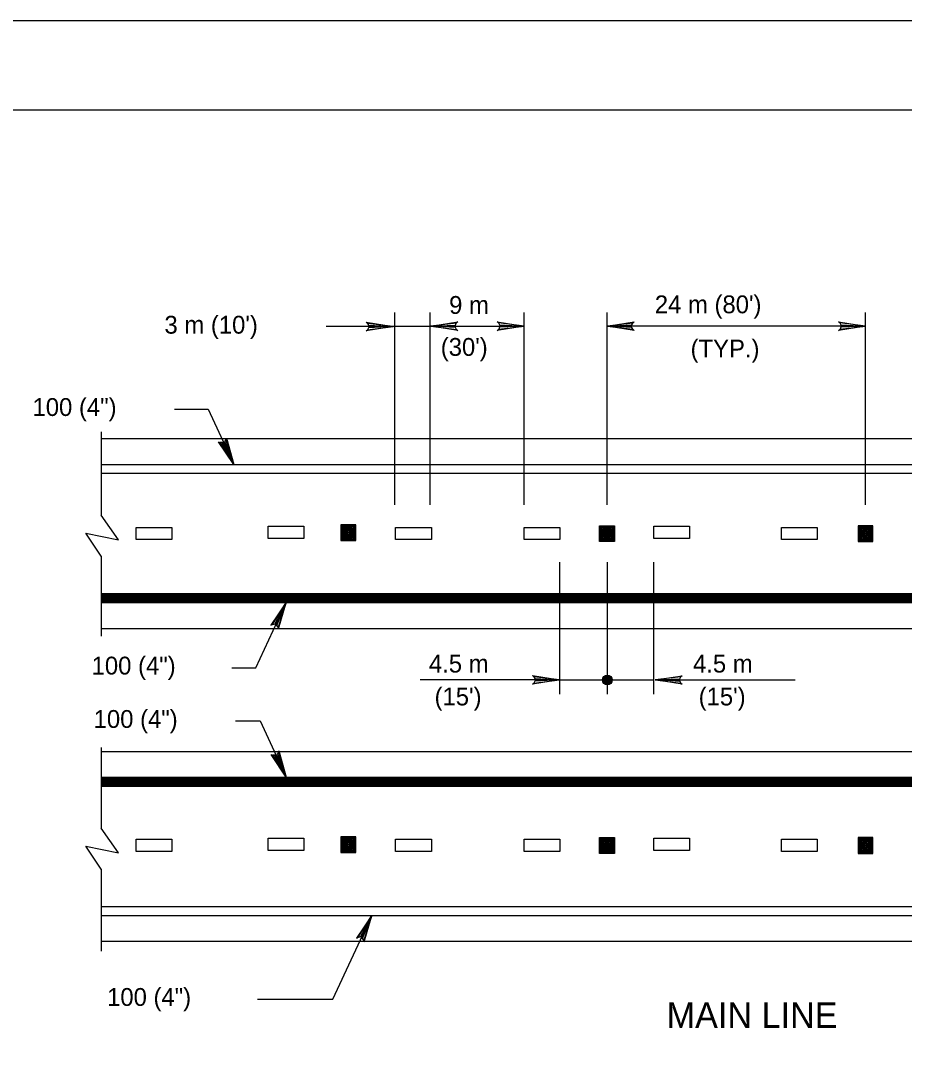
# Model space of a CAD drawing. Extents: x 639362 to 641108, y 298458 to 299646.
# Drawn here: x 639830.9 to 639979.6, y 299473.3 to 299645.6 of the extents above; entities that cross this region are included whole.
import ezdxf

# ---------------------------------------------------------------- set-up
doc = ezdxf.new("R2010")
doc.units = 0
for name, color, linetype in [('1', 7, 'Continuous'), ('2', 7, 'Continuous'), ('PLT-BNDY', 7, 'Continuous')]:
    doc.layers.add(name, color=color, linetype=linetype)

msp = doc.modelspace()

# ---------------------------------------------------------------- linework, layer by layer
at = {"layer": '1'}
msp.add_line((639402.31, 299630.63), (640188.31, 299630.63), dxfattribs=at)
at = {"layer": '2'}
for p, q in [((639893.88, 299564.2), (639893.88, 299596.53)), ((639899.82, 299564.2), (639899.82, 299596.53)), ((639915.64, 299564.2), (639915.64, 299596.53)), ((639929.6, 299564.2), (639929.6, 299596.53)), ((639973.04, 299564.2), (639973.04, 299596.53)), ((639882.34, 299594.23), (639899.82, 299594.23)), ((639899.82, 299594.23), (639915.64, 299594.23)), ((639973.04, 299594.23), (639929.6, 299594.23)), ((639856.81, 299580.26), (639862.49, 299580.26)), ((639862.49, 299580.26), (639866.8, 299570.98)), ((639844.48, 299576.44), (639844.48, 299562.41)), ((639844.48, 299575.33), (640078.99, 299575.33)), ((639844.48, 299570.98), (640078.99, 299570.98)), ((639844.48, 299569.48), (640078.99, 299569.48)), ((639847.43, 299558.27), (639844.48, 299562.41)), ((639850.37, 299558.33), (639850.37, 299560.39)), ((639850.37, 299560.39), (639856.39, 299560.39)), ((639856.39, 299560.39), (639856.39, 299558.33)), ((639872.56, 299558.51), (639872.56, 299560.58)), ((639872.56, 299560.58), (639878.58, 299560.58)), ((639878.58, 299560.58), (639878.58, 299558.51)), ((639887.32, 299560.81), (639884.82, 299560.81)), ((639884.82, 299560.81), (639884.82, 299558.16)), ((639887.13, 299560.68), (639885.01, 299560.68)), ((639885.01, 299560.68), (639885.01, 299558.29)), ((639886.96, 299560.51), (639885.18, 299560.51)), ((639885.18, 299560.51), (639885.18, 299558.47)), ((639886.78, 299560.33), (639885.36, 299560.33)), ((639885.36, 299560.33), (639885.36, 299558.64)), ((639886.6, 299560.15), (639885.54, 299560.15)), ((639885.54, 299560.15), (639885.54, 299558.82)), ((639886.6, 299558.82), (639886.6, 299560.15)), ((639886.78, 299558.64), (639886.78, 299560.33)), ((639886.96, 299558.47), (639886.96, 299560.51)), ((639887.13, 299558.29), (639887.13, 299560.68)), ((639887.32, 299558.16), (639887.32, 299560.81)), ((639894.01, 299558.33), (639894.01, 299560.39)), ((639894.01, 299560.39), (639900.02, 299560.39)), ((639900.02, 299560.39), (639900.02, 299558.33)), ((639915.64, 299558.33), (639915.64, 299560.39)), ((639915.64, 299560.39), (639921.65, 299560.39)), ((639921.65, 299560.39), (639921.65, 299558.33)), ((639928.31, 299560.65), (639930.81, 299560.65)), ((639928.31, 299558), (639928.31, 299560.65)), ((639928.5, 299560.52), (639930.63, 299560.52)), ((639928.5, 299558.12), (639928.5, 299560.52)), ((639928.68, 299560.34), (639930.45, 299560.34)), ((639928.68, 299558.3), (639928.68, 299560.34)), ((639928.85, 299560.16), (639930.27, 299560.16)), ((639928.85, 299558.48), (639928.85, 299560.16)), ((639930.27, 299560.16), (639930.27, 299558.48)), ((639930.45, 299560.34), (639930.45, 299558.3)), ((639930.63, 299560.52), (639930.63, 299558.12)), ((639930.81, 299560.65), (639930.81, 299558)), ((639937.42, 299558.51), (639937.42, 299560.58)), ((639937.42, 299560.58), (639943.44, 299560.58)), ((639943.44, 299560.58), (639943.44, 299558.51)), ((639958.88, 299558.33), (639958.88, 299560.39)), ((639958.88, 299560.39), (639964.89, 299560.39)), ((639964.89, 299560.39), (639964.89, 299558.33)), ((639974.28, 299560.65), (639971.78, 299560.65)), ((639971.78, 299560.65), (639971.78, 299558)), ((639974.09, 299560.52), (639971.96, 299560.52)), ((639971.96, 299560.52), (639971.96, 299558.12)), ((639973.92, 299560.34), (639972.14, 299560.34)), ((639972.14, 299560.34), (639972.14, 299558.3)), ((639973.74, 299560.16), (639972.32, 299560.16)), ((639972.32, 299560.16), (639972.32, 299558.48)), ((639973.74, 299558.48), (639973.74, 299560.16)), ((639973.92, 299558.3), (639973.92, 299560.34)), ((639974.09, 299558.12), (639974.09, 299560.52)), ((639974.28, 299558), (639974.28, 299560.65)), ((639844.48, 299555.54), (639841.91, 299559.41)), ((639841.91, 299559.41), (639847.43, 299558.27)), ((639878.58, 299558.51), (639872.56, 299558.51)), ((639885.18, 299558.47), (639886.96, 299558.47)), ((639885.36, 299558.64), (639886.78, 299558.64)), ((639885.54, 299558.82), (639886.6, 299558.82)), ((639885.71, 299559.97), (639885.71, 299559)), ((639886.43, 299559.97), (639885.71, 299559.97)), ((639885.71, 299559), (639886.43, 299559)), ((639886.25, 299559.79), (639885.89, 299559.79)), ((639885.89, 299559.79), (639885.89, 299559.17)), ((639885.89, 299559.17), (639886.25, 299559.17)), ((639886.07, 299559.62), (639886.07, 299559.35)), ((639886.25, 299559.17), (639886.25, 299559.79)), ((639886.43, 299559), (639886.43, 299559.97)), ((639930.27, 299558.48), (639928.85, 299558.48)), ((639929.03, 299559.99), (639930.1, 299559.99)), ((639929.03, 299558.66), (639929.03, 299559.99)), ((639930.1, 299558.66), (639929.03, 299558.66)), ((639929.21, 299558.83), (639929.21, 299559.81)), ((639929.21, 299559.81), (639929.92, 299559.81)), ((639929.92, 299558.83), (639929.21, 299558.83)), ((639929.39, 299559.63), (639929.74, 299559.63)), ((639929.39, 299559.01), (639929.39, 299559.63)), ((639929.74, 299559.01), (639929.39, 299559.01)), ((639929.56, 299559.45), (639929.56, 299559.19)), ((639929.74, 299559.63), (639929.74, 299559.01)), ((639929.92, 299559.81), (639929.92, 299558.83)), ((639930.1, 299559.99), (639930.1, 299558.66)), ((639943.44, 299558.51), (639937.42, 299558.51)), ((639972.32, 299558.48), (639973.74, 299558.48)), ((639973.56, 299559.99), (639972.5, 299559.99)), ((639972.5, 299559.99), (639972.5, 299558.66)), ((639972.5, 299558.66), (639973.56, 299558.66)), ((639972.67, 299559.81), (639972.67, 299558.83)), ((639973.38, 299559.81), (639972.67, 299559.81)), ((639972.67, 299558.83), (639973.38, 299558.83)), ((639973.2, 299559.63), (639972.85, 299559.63)), ((639972.85, 299559.63), (639972.85, 299559.01)), ((639972.85, 299559.01), (639973.2, 299559.01)), ((639973.03, 299559.45), (639973.03, 299559.19)), ((639973.2, 299559.01), (639973.2, 299559.63)), ((639973.38, 299558.83), (639973.38, 299559.81)), ((639973.56, 299558.66), (639973.56, 299559.99)), ((639856.39, 299558.33), (639850.37, 299558.33)), ((639884.82, 299558.16), (639887.32, 299558.16)), ((639885.01, 299558.29), (639887.13, 299558.29)), ((639900.02, 299558.33), (639894.01, 299558.33)), ((639921.65, 299558.33), (639915.64, 299558.33)), ((639930.81, 299558), (639928.31, 299558)), ((639930.63, 299558.12), (639928.5, 299558.12)), ((639930.45, 299558.3), (639928.68, 299558.3)), ((639964.89, 299558.33), (639958.88, 299558.33)), ((639971.78, 299558), (639974.28, 299558)), ((639971.96, 299558.12), (639974.09, 299558.12)), ((639972.14, 299558.3), (639973.92, 299558.3)), ((639844.48, 299555.54), (639844.48, 299542.1)), ((639921.57, 299554.52), (639921.57, 299532.35)), ((639929.6, 299554.52), (639929.6, 299532.35)), ((639937.4, 299554.52), (639937.4, 299532.35)), ((639844.48, 299549.24), (640078.99, 299549.24)), ((639844.48, 299549.09), (640078.99, 299549.09)), ((639844.48, 299548.94), (640078.99, 299548.94)), ((639844.48, 299548.79), (640078.99, 299548.79)), ((639844.48, 299548.64), (640078.99, 299548.64)), ((639844.48, 299548.49), (640078.99, 299548.49)), ((639844.48, 299548.34), (640078.99, 299548.34)), ((639844.48, 299548.19), (640078.99, 299548.19)), ((639844.48, 299548.04), (640078.99, 299548.04)), ((639844.48, 299547.89), (640078.99, 299547.89)), ((639844.48, 299547.74), (640078.99, 299547.74)), ((639870.5, 299536.76), (639875.59, 299547.74)), ((639844.48, 299543.39), (640078.99, 299543.39)), ((639866.45, 299536.76), (639870.5, 299536.76)), ((639921.57, 299534.72), (639898.14, 299534.72)), ((639921.57, 299534.72), (639937.4, 299534.72)), ((639937.63, 299534.72), (639961.2, 299534.72)), ((639867.08, 299527.87), (639871.22, 299527.87)), ((639871.22, 299527.87), (639875.63, 299518.37)), ((639844.48, 299523.39), (639844.48, 299509.8)), ((639844.48, 299522.72), (640078.99, 299522.72)), ((639844.48, 299518.37), (640078.99, 299518.37)), ((639844.48, 299518.22), (640078.99, 299518.22)), ((639844.48, 299518.07), (640078.99, 299518.07)), ((639844.48, 299517.92), (640078.99, 299517.92)), ((639844.48, 299517.77), (640078.99, 299517.77)), ((639844.48, 299517.62), (640078.99, 299517.62)), ((639844.48, 299517.47), (640078.99, 299517.47)), ((639844.48, 299517.32), (640078.99, 299517.32)), ((639844.48, 299517.17), (640078.99, 299517.17)), ((639844.48, 299517.02), (640078.99, 299517.02)), ((639844.48, 299516.87), (640078.99, 299516.87)), ((639847.43, 299505.67), (639844.48, 299509.8)), ((639844.48, 299502.93), (639841.91, 299506.8)), ((639841.91, 299506.8), (639847.43, 299505.67)), ((639850.37, 299505.88), (639850.37, 299507.94)), ((639850.37, 299507.94), (639856.39, 299507.94)), ((639856.39, 299507.94), (639856.39, 299505.88)), ((639872.56, 299506.07), (639872.56, 299508.13)), ((639872.56, 299508.13), (639878.58, 299508.13)), ((639878.58, 299508.13), (639878.58, 299506.07)), ((639887.32, 299508.37), (639884.82, 299508.37)), ((639884.82, 299508.37), (639884.82, 299505.71)), ((639887.13, 299508.24), (639885.01, 299508.24)), ((639885.01, 299508.24), (639885.01, 299505.84)), ((639886.96, 299508.06), (639885.18, 299508.06)), ((639885.18, 299508.06), (639885.18, 299506.02)), ((639886.78, 299507.88), (639885.36, 299507.88)), ((639885.36, 299507.88), (639885.36, 299506.2)), ((639886.6, 299507.7), (639885.54, 299507.7)), ((639885.54, 299507.7), (639885.54, 299506.37)), ((639885.71, 299507.53), (639885.71, 299506.55)), ((639886.43, 299507.53), (639885.71, 299507.53)), ((639886.25, 299507.35), (639885.89, 299507.35)), ((639885.89, 299507.35), (639885.89, 299506.73)), ((639885.89, 299506.73), (639886.25, 299506.73)), ((639886.07, 299507.17), (639886.07, 299506.91)), ((639886.25, 299506.73), (639886.25, 299507.35)), ((639886.43, 299506.55), (639886.43, 299507.53)), ((639886.6, 299506.37), (639886.6, 299507.7)), ((639886.78, 299506.2), (639886.78, 299507.88)), ((639886.96, 299506.02), (639886.96, 299508.06)), ((639887.13, 299505.84), (639887.13, 299508.24)), ((639887.32, 299505.71), (639887.32, 299508.37)), ((639894.01, 299505.88), (639894.01, 299507.94)), ((639894.01, 299507.94), (639900.02, 299507.94)), ((639900.02, 299507.94), (639900.02, 299505.88)), ((639915.64, 299505.88), (639915.64, 299507.94)), ((639915.64, 299507.94), (639921.65, 299507.94)), ((639921.65, 299507.94), (639921.65, 299505.88)), ((639928.31, 299508.21), (639930.81, 299508.21)), ((639928.31, 299505.55), (639928.31, 299508.21)), ((639928.5, 299508.07), (639930.63, 299508.07)), ((639928.5, 299505.68), (639928.5, 299508.07)), ((639928.68, 299507.9), (639930.45, 299507.9)), ((639928.68, 299505.86), (639928.68, 299507.9)), ((639928.85, 299507.72), (639930.27, 299507.72)), ((639928.85, 299506.03), (639928.85, 299507.72)), ((639929.03, 299507.54), (639930.1, 299507.54)), ((639929.03, 299506.21), (639929.03, 299507.54)), ((639929.21, 299506.39), (639929.21, 299507.36)), ((639929.21, 299507.36), (639929.92, 299507.36)), ((639929.39, 299507.19), (639929.74, 299507.19)), ((639929.39, 299506.57), (639929.39, 299507.19)), ((639929.56, 299507.01), (639929.56, 299506.74)), ((639929.74, 299507.19), (639929.74, 299506.57)), ((639929.92, 299507.36), (639929.92, 299506.39)), ((639930.1, 299507.54), (639930.1, 299506.21)), ((639930.27, 299507.72), (639930.27, 299506.03)), ((639930.45, 299507.9), (639930.45, 299505.86)), ((639930.63, 299508.07), (639930.63, 299505.68)), ((639930.81, 299508.21), (639930.81, 299505.55)), ((639937.42, 299506.07), (639937.42, 299508.13)), ((639937.42, 299508.13), (639943.44, 299508.13)), ((639943.44, 299508.13), (639943.44, 299506.07)), ((639958.88, 299505.88), (639958.88, 299507.94)), ((639958.88, 299507.94), (639964.89, 299507.94)), ((639964.89, 299507.94), (639964.89, 299505.88)), ((639974.28, 299508.21), (639971.78, 299508.21)), ((639971.78, 299508.21), (639971.78, 299505.55)), ((639974.09, 299508.07), (639971.96, 299508.07)), ((639971.96, 299508.07), (639971.96, 299505.68)), ((639973.92, 299507.9), (639972.14, 299507.9)), ((639972.14, 299507.9), (639972.14, 299505.86)), ((639973.74, 299507.72), (639972.32, 299507.72)), ((639972.32, 299507.72), (639972.32, 299506.03)), ((639973.56, 299507.54), (639972.5, 299507.54)), ((639972.5, 299507.54), (639972.5, 299506.21)), ((639972.67, 299507.36), (639972.67, 299506.39)), ((639973.38, 299507.36), (639972.67, 299507.36)), ((639973.2, 299507.19), (639972.85, 299507.19)), ((639972.85, 299507.19), (639972.85, 299506.57)), ((639973.03, 299507.01), (639973.03, 299506.74)), ((639973.2, 299506.57), (639973.2, 299507.19)), ((639973.38, 299506.39), (639973.38, 299507.36)), ((639973.56, 299506.21), (639973.56, 299507.54)), ((639973.74, 299506.03), (639973.74, 299507.72)), ((639973.92, 299505.86), (639973.92, 299507.9)), ((639974.09, 299505.68), (639974.09, 299508.07)), ((639974.28, 299505.55), (639974.28, 299508.21)), ((639856.39, 299505.88), (639850.37, 299505.88)), ((639878.58, 299506.07), (639872.56, 299506.07)), ((639884.82, 299505.71), (639887.32, 299505.71)), ((639885.01, 299505.84), (639887.13, 299505.84)), ((639885.18, 299506.02), (639886.96, 299506.02)), ((639885.36, 299506.2), (639886.78, 299506.2)), ((639885.54, 299506.37), (639886.6, 299506.37)), ((639885.71, 299506.55), (639886.43, 299506.55)), ((639900.02, 299505.88), (639894.01, 299505.88)), ((639921.65, 299505.88), (639915.64, 299505.88)), ((639930.81, 299505.55), (639928.31, 299505.55)), ((639930.63, 299505.68), (639928.5, 299505.68)), ((639930.45, 299505.86), (639928.68, 299505.86)), ((639930.27, 299506.03), (639928.85, 299506.03)), ((639930.1, 299506.21), (639929.03, 299506.21)), ((639929.92, 299506.39), (639929.21, 299506.39)), ((639929.74, 299506.57), (639929.39, 299506.57)), ((639943.44, 299506.07), (639937.42, 299506.07)), ((639964.89, 299505.88), (639958.88, 299505.88)), ((639971.78, 299505.55), (639974.28, 299505.55)), ((639971.96, 299505.68), (639974.09, 299505.68)), ((639972.14, 299505.86), (639973.92, 299505.86)), ((639972.32, 299506.03), (639973.74, 299506.03)), ((639972.5, 299506.21), (639973.56, 299506.21)), ((639972.67, 299506.39), (639973.38, 299506.39)), ((639972.85, 299506.57), (639973.2, 299506.57)), ((639844.48, 299502.93), (639844.48, 299489.11)), ((639844.48, 299496.64), (640078.99, 299496.64)), ((639844.48, 299495.14), (640078.99, 299495.14)), ((639883.47, 299481.07), (639890, 299495.14)), ((639844.48, 299490.79), (640078.99, 299490.79)), ((639870.78, 299481.07), (639883.47, 299481.07))]:
    msp.add_line(p, q, dxfattribs=at)
for points in [[(639889.26, 299594.69), (639889.43, 299594.38), (639893.58, 299594.15), (639889.26, 299594.69), (639889.05, 299594.88), (639893.58, 299594.15), (639889.43, 299593.94), (639889.28, 299593.63), (639893.58, 299594.15), (639889.05, 299593.43), (639889.28, 299593.63)], [(639904.23, 299593.67), (639904.07, 299593.97), (639899.91, 299594.2), (639904.23, 299593.67), (639904.45, 299593.47), (639899.91, 299594.2), (639904.07, 299594.41), (639904.22, 299594.72), (639899.91, 299594.2), (639904.45, 299594.93), (639904.22, 299594.72)], [(639911.32, 299594.77), (639911.48, 299594.46), (639915.64, 299594.23), (639911.32, 299594.77), (639911.11, 299594.96), (639915.64, 299594.23), (639911.49, 299594.03), (639911.34, 299593.72), (639915.64, 299594.23), (639911.11, 299593.51), (639911.34, 299593.72)], [(639933.92, 299593.69), (639933.76, 299594), (639929.6, 299594.23), (639933.92, 299593.69), (639934.14, 299593.5), (639929.6, 299594.23), (639933.76, 299594.44), (639933.91, 299594.75), (639929.6, 299594.23), (639934.14, 299594.95), (639933.91, 299594.75)], [(639968.73, 299594.77), (639968.89, 299594.46), (639973.04, 299594.23), (639968.73, 299594.77), (639968.5, 299594.96), (639973.04, 299594.23), (639968.89, 299594.03), (639968.74, 299593.72), (639973.04, 299594.23), (639968.5, 299593.51), (639968.74, 299593.72)], [(639865.47, 299575.12), (639865.26, 299574.85), (639866.8, 299570.98), (639865.47, 299575.12), (639865.55, 299575.4), (639866.8, 299570.98), (639864.87, 299574.66), (639864.52, 299574.66), (639866.8, 299570.98), (639864.23, 299574.79), (639864.52, 299574.66)], [(639874.26, 299543.6), (639874.05, 299543.87), (639875.59, 299547.74), (639874.26, 299543.6), (639874.34, 299543.32), (639875.59, 299547.74), (639873.66, 299544.06), (639873.31, 299544.05), (639875.59, 299547.74), (639873.03, 299543.93), (639873.31, 299544.05)], [(639917.26, 299535.26), (639917.42, 299534.95), (639921.57, 299534.72), (639917.26, 299535.26), (639917.04, 299535.45), (639921.57, 299534.72), (639917.42, 299534.52), (639917.27, 299534.2), (639921.57, 299534.72), (639917.04, 299534), (639917.27, 299534.2)], [(639942, 299534.18), (639941.84, 299534.49), (639937.68, 299534.72), (639942, 299534.18), (639942.22, 299533.99), (639937.68, 299534.72), (639941.83, 299534.92), (639941.99, 299535.23), (639937.68, 299534.72), (639942.22, 299535.44), (639941.99, 299535.23)], [(639874.3, 299522.51), (639874.09, 299522.24), (639875.63, 299518.37), (639874.3, 299522.51), (639874.38, 299522.79), (639875.63, 299518.37), (639873.69, 299522.05), (639873.35, 299522.06), (639875.63, 299518.37), (639873.06, 299522.18), (639873.35, 299522.06)], [(639888.67, 299490.99), (639888.46, 299491.27), (639890, 299495.14), (639888.67, 299490.99), (639888.75, 299490.71), (639890, 299495.14), (639888.07, 299491.45), (639887.72, 299491.45), (639890, 299495.14), (639887.43, 299491.32), (639887.72, 299491.45)]]:
    msp.add_lwpolyline(points, dxfattribs=at)
for radius in [0.817, 0.759, 0.701, 0.643, 0.585, 0.527, 0.469, 0.411, 0.353, 0.295, 0.237, 0.179, 0.121, 0.0627]:
    msp.add_circle((639929.6, 299534.72), radius, dxfattribs=at)
at = {"layer": 'PLT-BNDY'}
msp.add_lwpolyline([(639362.31, 299645.63), (640203.31, 299645.63), (640203.31, 299051.63), (639362.31, 299051.63)], close=True, dxfattribs=at)

# ---------------------------------------------------------------- texts
at = {"layer": '2'}
for s, height, p in [('9 m', 3, (639903.01, 299596.29)), ("24 m (80')", 3, (639937.6, 299596.39)), ("3 m (10')", 3, (639855.14, 299592.96)), ("(30')", 3, (639901.6, 299589.23)), ('(TYP.)', 3, (639943.61, 299588.96)), ('100 (4")', 3, (639832.95, 299579.12)), ('100 (4")', 3, (639842.89, 299535.64)), ('4.5 m', 3, (639899.61, 299535.97)), ('4.5 m', 3, (639944.02, 299535.97)), ("(15')", 3, (639900.56, 299530.44)), ("(15')", 3, (639944.97, 299530.44)), ('100 (4")', 3, (639843.23, 299526.66)), ('100 (4")', 3, (639845.49, 299479.91)), ('MAIN LINE', 4.3, (639939.58, 299476.2))]:
    msp.add_text(s, height=height, dxfattribs=at).set_placement(p)

doc.saveas('drawing.dxf')
